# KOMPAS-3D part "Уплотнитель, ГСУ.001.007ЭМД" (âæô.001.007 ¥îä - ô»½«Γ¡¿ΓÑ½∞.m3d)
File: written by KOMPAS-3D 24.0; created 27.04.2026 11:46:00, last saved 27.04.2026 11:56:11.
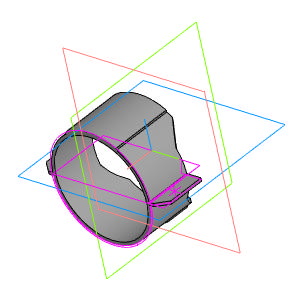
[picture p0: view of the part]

Document properties: Автор: USG_411; Полное имя файла: C:\Users\USG_411.STUD\Desktop\ГМ2704_411-23\Двигатель мясорубки\ГСУ.001.007 ЭМД - Уплотнитель.m3d

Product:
- Part/product: Уплотнитель  | designation ГСУ.001.007ЭМД
    Масса: 0.017756

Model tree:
1. Эскиз:1
2. Элемент выдавливания:1
     Расстояние 1 = 20
3. Эскиз:2  (with: Грань.Элемент выдавливания:1, Ребро.Элемент выдавливания:1)
4. Элемент выдавливания:2
     Расстояние 1 = 50
5. Эскиз:3  (with: Ребро.Элемент выдавливания:1, Грань.Элемент выдавливания:1)
6. Элемент выдавливания:3
     Расстояние 1 = 1
7. Зеркальный массив:1
8. Экземпляр ( 1 )
9. Экземпляр ( 2 )  (with: Элемент выдавливания:3, Элемент выдавливания:2)
10. Эскиз:4  (with: Грань.Элемент выдавливания:1, Ребро.Элемент выдавливания:1)
11. Элемент выдавливания:4
     Расстояние 2 = 20
12. Элемент выдавливания:5
     Расстояние 2 = 12
13. Зеркальный массив:2  (with: Экземпляр ( 1 ), Экземпляр ( 2 ), Элемент выдавливания:4)

Expressions: 21.4/2
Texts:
  ГСУ.001.007
  ГСУ.001.007 ЭМД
